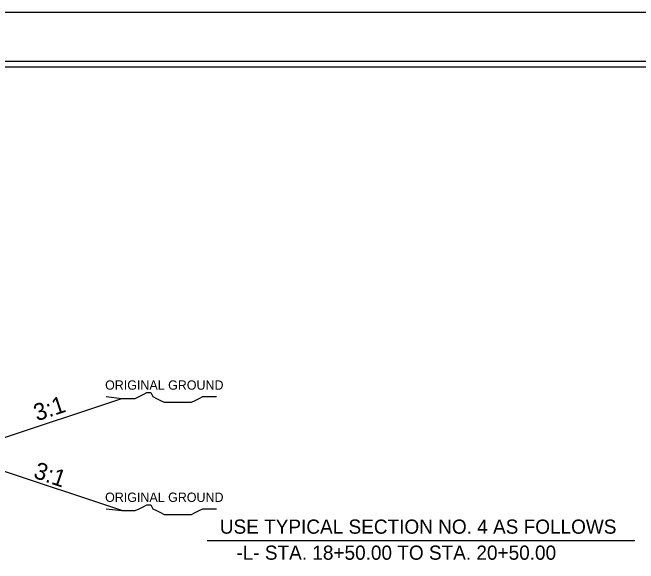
# Model space of a CAD drawing. Extents: x 957297 to 961629, y 830661 to 840840.
# Drawn here: x 959889 to 960176, y 838053.5 to 838306.3 of the extents above; entities that cross this region are included whole.
import ezdxf

# ---------------------------------------------------------------- set-up
doc = ezdxf.new("R2010")
doc.units = 0
for name, color, linetype in [('Old_Level_1', 7, 'Continuous'), ('Old_Level_21', 7, 'Continuous'), ('Old_Level_3', 7, 'Continuous'), ('Sheet Plot Border Inside CELL', 7, 'Continuous'), ('Sheet Plot Border Outside CELL', 7, 'Continuous'), ('Sheet Typical CELL', 7, 'Continuous')]:
    doc.layers.add(name, color=color, linetype=linetype)

msp = doc.modelspace()

# ---------------------------------------------------------------- linework, layer by layer
at = {"layer": 'Old_Level_1'}
for p, q in [((959861.91, 838103.52), (959939.1, 838129.25)), ((959939.1, 838077.78), (959861.91, 838103.52)), ((959978.32, 838064.06), (960174.26, 838064.06))]:
    msp.add_line(p, q, dxfattribs=at)
at = {"layer": 'Old_Level_21'}
for points in [[(959932, 838130.13), (959939.1, 838129.25), (959940.87, 838129.25), (959943.53, 838129.25), (959945.31, 838129.25), (959947.08, 838130.13), (959948.85, 838131.02), (959950.62, 838131.91), (959952.4, 838131.91), (959953.3, 838130.13), (959955.06, 838129.25), (959956.84, 838128.35), (959958.61, 838127.48), (959960.38, 838127.48), (959962.15, 838127.48), (959963.93, 838127.48), (959965.7, 838127.48), (959967.48, 838127.48), (959969.25, 838127.48), (959971.02, 838127.48), (959972.79, 838128.35), (959974.56, 838129.25), (959976.33, 838130.13), (959979.01, 838130.13), (959980.78, 838130.13), (959982.55, 838130.13)], [(959932, 838078.67), (959939.1, 838077.78), (959940.87, 838077.78), (959943.53, 838077.78), (959945.31, 838077.78), (959947.08, 838078.67), (959948.85, 838079.56), (959950.62, 838080.44), (959952.4, 838080.44), (959953.3, 838078.67), (959955.06, 838077.78), (959956.84, 838076.89), (959958.61, 838076.01), (959960.38, 838076.01), (959962.15, 838076.01), (959963.93, 838076.01), (959965.7, 838076.01), (959967.48, 838076.01), (959969.25, 838076.01), (959971.02, 838076.01), (959972.79, 838076.89), (959974.56, 838077.78), (959976.33, 838078.67), (959979.01, 838078.67), (959980.78, 838078.67), (959982.55, 838078.67)]]:
    msp.add_lwpolyline(points, dxfattribs=at)
at = {"layer": 'Sheet Plot Border Inside CELL'}
msp.add_lwpolyline([(960390.3, 838283.82), (958723.8, 838283.82), (958723.8, 837228.72), (960390.3, 837228.72)], close=True, dxfattribs=at)
at = {"layer": 'Sheet Plot Border Outside CELL'}
msp.add_lwpolyline([(960394.8, 838306.27), (958710.8, 838306.27), (958710.8, 837206.27), (960394.8, 837206.27)], close=True, dxfattribs=at)
at = {"layer": 'Sheet Typical CELL'}
msp.add_lwpolyline([(960377.8, 838281.27), (958877.8, 838281.27), (958877.8, 837231.27), (960377.8, 837231.27)], close=True, dxfattribs=at)

# ---------------------------------------------------------------- texts
at = {"layer": 'Old_Level_1'}
for s, p in [('USE TYPICAL SECTION NO. 4 AS FOLLOWS', (959984.05, 838067.18)), ('-L- STA. 18+50.00 TO STA. 20+50.00', (959991.64, 838055.24))]:
    msp.add_text(s, height=6.5088, dxfattribs=at).set_placement(p)
at = {"layer": 'Old_Level_21'}
for p in [(959931.46, 838133.24), (959931.46, 838081.78)]:
    msp.add_text('ORIGINAL GROUND', height=4.2722, dxfattribs=at).set_placement(p)
at = {"layer": 'Old_Level_3'}
for rotation, p in [(18.4348, (959900.21, 838118.7)), (341.0454, (959898.15, 838093.01))]:
    msp.add_text('3:1', height=7.801, rotation=rotation, dxfattribs=at).set_placement(p)

doc.saveas('drawing.dxf')
